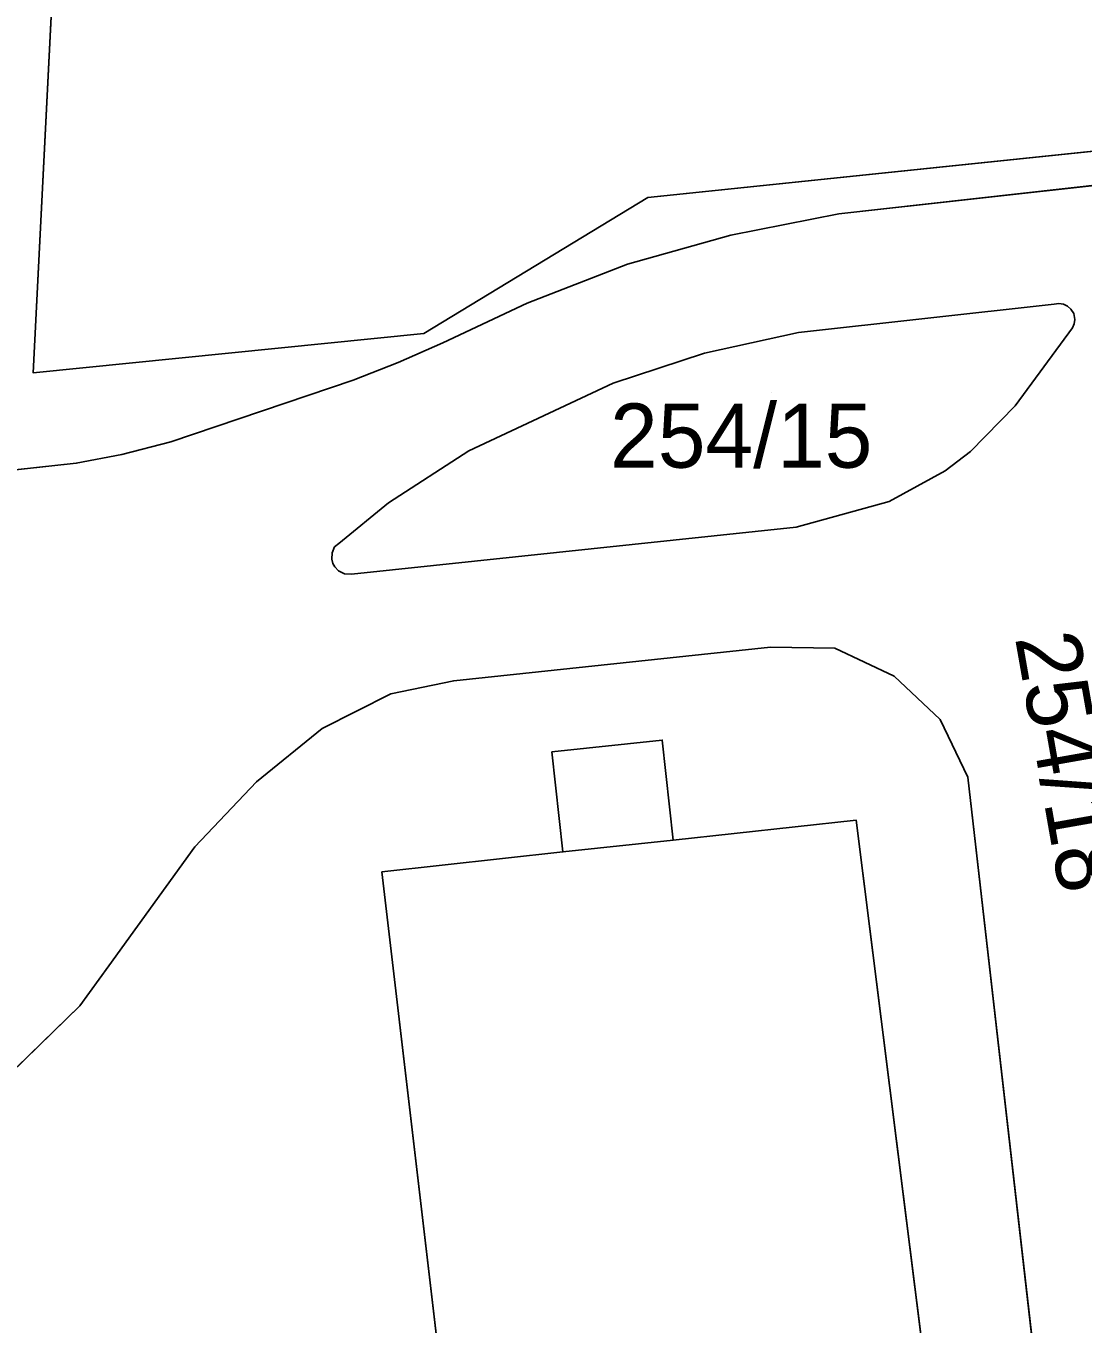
# Model space of a CAD drawing. Extents: x -263423 to -261326, y -1240067 to -1237864.
# Drawn here: x -263309.81 to -263276.85, y -1239534.41 to -1239493.95 of the extents above; entities that cross this region are included whole.
import ezdxf

# ---------------------------------------------------------------- set-up
doc = ezdxf.new("R2010")
doc.units = 0
for name, color, linetype in [('body_kn', 7, 'Continuous'), ('kladpar_druhypozemkov', 7, 'Continuous'), ('kladpar_hranice', 7, 'Continuous'), ('kladpar_parcelnecisla', 7, 'Continuous'), ('kladpar_plochy', 7, 'Continuous'), ('zappar_hrandruhpozemk', 7, 'Continuous')]:
    doc.layers.add(name, color=color, linetype=linetype)

msp = doc.modelspace()

# ---------------------------------------------------------------- linework, layer by layer
at = {"layer": 'body_kn'}
for p, q in [((-263290.42, -1239499.3), (-263290.42, -1239499.3)), ((-263284.46, -1239499.81), (-263284.46, -1239499.81)), ((-263287.83, -1239500.47), (-263287.83, -1239500.47)), ((-263291.05, -1239501.38), (-263291.05, -1239501.38)), ((-263294.18, -1239502.59), (-263294.18, -1239502.59)), ((-263277.75, -1239502.62), (-263277.75, -1239502.62)), ((-263277.61, -1239502.6), (-263277.61, -1239502.6)), ((-263277.46, -1239502.62), (-263277.46, -1239502.62)), ((-263277.33, -1239502.68), (-263277.33, -1239502.68)), ((-263277.23, -1239502.78), (-263277.23, -1239502.78)), ((-263277.14, -1239502.91), (-263277.14, -1239502.91)), ((-263277.13, -1239503.24), (-263277.13, -1239503.24)), ((-263277.11, -1239503.1), (-263277.11, -1239503.1)), ((-263297.4, -1239503.54), (-263297.4, -1239503.54)), ((-263285.72, -1239503.51), (-263285.72, -1239503.51)), ((-263277.18, -1239503.36), (-263277.18, -1239503.36)), ((-263296.81, -1239503.83), (-263296.81, -1239503.83)), ((-263298.2, -1239504.44), (-263298.2, -1239504.44)), ((-263288.65, -1239504.15), (-263288.65, -1239504.15)), ((-263309.59, -1239504.76), (-263309.59, -1239504.76)), ((-263299.61, -1239504.99), (-263299.61, -1239504.99)), ((-263291.5, -1239505.09), (-263291.5, -1239505.09)), ((-263278.97, -1239505.79), (-263278.97, -1239505.79)), ((-263305.29, -1239506.91), (-263305.29, -1239506.91)), ((-263296, -1239507.19), (-263296, -1239507.19)), ((-263280.36, -1239507.22), (-263280.36, -1239507.22)), ((-263308.24, -1239507.58), (-263308.24, -1239507.58)), ((-263306.82, -1239507.31), (-263306.82, -1239507.31)), ((-263281.15, -1239507.82), (-263281.15, -1239507.82)), ((-263298.51, -1239508.82), (-263298.51, -1239508.82)), ((-263298.51, -1239508.82), (-263298.51, -1239508.82)), ((-263282.9, -1239508.77), (-263282.9, -1239508.77)), ((-263285.79, -1239509.57), (-263285.79, -1239509.57)), ((-263300.05, -1239510.08), (-263300.05, -1239510.08)), ((-263300.26, -1239510.37), (-263300.26, -1239510.37)), ((-263300.19, -1239510.19), (-263300.19, -1239510.19)), ((-263300.27, -1239510.57), (-263300.27, -1239510.57)), ((-263300.24, -1239510.71), (-263300.24, -1239510.71)), ((-263300.18, -1239510.81), (-263300.18, -1239510.81)), ((-263300.07, -1239510.94), (-263300.07, -1239510.94)), ((-263299.88, -1239511.03), (-263299.88, -1239511.03)), ((-263299.66, -1239511.04), (-263299.66, -1239511.04)), ((-263286.59, -1239513.31), (-263286.59, -1239513.31)), ((-263284.59, -1239513.35), (-263284.59, -1239513.35)), ((-263296.47, -1239514.36), (-263296.47, -1239514.36)), ((-263282.74, -1239514.22), (-263282.74, -1239514.22)), ((-263298.43, -1239514.77), (-263298.43, -1239514.77)), ((-263281.3, -1239515.57), (-263281.3, -1239515.57)), ((-263300.57, -1239515.85), (-263300.57, -1239515.85)), ((-263293.41, -1239516.58), (-263293.41, -1239516.58)), ((-263289.97, -1239516.21), (-263289.97, -1239516.21)), ((-263280.44, -1239517.37), (-263280.44, -1239517.37)), ((-263302.62, -1239517.51), (-263302.62, -1239517.51)), ((-263283.92, -1239518.71), (-263283.92, -1239518.71)), ((-263289.63, -1239519.33), (-263289.63, -1239519.33)), ((-263304.54, -1239519.54), (-263304.54, -1239519.54)), ((-263293.07, -1239519.7), (-263293.07, -1239519.7)), ((-263293.07, -1239519.7), (-263293.07, -1239519.7)), ((-263298.71, -1239520.32), (-263298.71, -1239520.32)), ((-263298.71, -1239520.32), (-263298.71, -1239520.32)), ((-263307.23, -1239523.25), (-263307.23, -1239523.25)), ((-263308.13, -1239524.5), (-263308.13, -1239524.5))]:
    msp.add_line(p, q, dxfattribs=at)
at = {"layer": 'kladpar_druhypozemkov'}
msp.add_line((-263286.55, -1239505.37), (-263286.55, -1239505.37), dxfattribs=at)
at = {"layer": 'kladpar_hranice'}
for points in [[(-263266.8, -1239496.84), (-263270.06, -1239468.65), (-263281.55, -1239470.13), (-263281.76, -1239468.51), (-263288.17, -1239469.5), (-263287.73, -1239473.48), (-263293.36, -1239474.1), (-263293.55, -1239472.76), (-263301.84, -1239473.75), (-263301.82, -1239475.02), (-263310.21, -1239475.95), (-263308.82, -1239489.52), (-263309.59, -1239504.76), (-263297.4, -1239503.54), (-263290.42, -1239499.3), (-263266.8, -1239496.84)], [(-263266.8, -1239496.84), (-263290.42, -1239499.3), (-263297.4, -1239503.54), (-263309.59, -1239504.76), (-263308.82, -1239489.52), (-263310.21, -1239475.95), (-263301.82, -1239475.02), (-263301.84, -1239473.75), (-263293.55, -1239472.76), (-263293.36, -1239474.1), (-263287.73, -1239473.48), (-263288.17, -1239469.5), (-263281.76, -1239468.51), (-263281.55, -1239470.13), (-263270.06, -1239468.65), (-263266.8, -1239496.84)], [(-263299.61, -1239504.99), (-263298.2, -1239504.44), (-263296.81, -1239503.83), (-263294.18, -1239502.59), (-263291.05, -1239501.38), (-263287.83, -1239500.47), (-263284.46, -1239499.81), (-263267.57, -1239497.92), (-263265.57, -1239497.54), (-263263.67, -1239496.95), (-263261.73, -1239496.38), (-263259.76, -1239496.02), (-263245.74, -1239494.34)], [(-263267.57, -1239497.92), (-263284.46, -1239499.81), (-263287.83, -1239500.47), (-263291.05, -1239501.38), (-263294.18, -1239502.59), (-263296.81, -1239503.83), (-263298.2, -1239504.44), (-263299.61, -1239504.99), (-263305.29, -1239506.91), (-263306.82, -1239507.31), (-263308.24, -1239507.58), (-263325.13, -1239509.43)], [(-263298.51, -1239508.82), (-263296, -1239507.19), (-263291.5, -1239505.09), (-263288.65, -1239504.15), (-263285.72, -1239503.51), (-263277.75, -1239502.62), (-263277.61, -1239502.6), (-263277.46, -1239502.62), (-263277.33, -1239502.68), (-263277.23, -1239502.78), (-263277.14, -1239502.91), (-263277.11, -1239503.1), (-263277.13, -1239503.24), (-263277.18, -1239503.36), (-263278.97, -1239505.79), (-263280.36, -1239507.22), (-263281.15, -1239507.82), (-263282.9, -1239508.77), (-263285.79, -1239509.57), (-263299.66, -1239511.04), (-263299.88, -1239511.03), (-263300.07, -1239510.94), (-263300.18, -1239510.81), (-263300.24, -1239510.71), (-263300.27, -1239510.57), (-263300.26, -1239510.37), (-263300.19, -1239510.19), (-263300.05, -1239510.08), (-263298.51, -1239508.82)], [(-263296, -1239507.19), (-263298.51, -1239508.82), (-263300.05, -1239510.08), (-263300.19, -1239510.19), (-263300.26, -1239510.37), (-263300.27, -1239510.57), (-263300.24, -1239510.71), (-263300.18, -1239510.81), (-263300.07, -1239510.94), (-263299.88, -1239511.03), (-263299.66, -1239511.04), (-263285.79, -1239509.57), (-263282.9, -1239508.77), (-263281.15, -1239507.82), (-263280.36, -1239507.22), (-263278.97, -1239505.79), (-263277.18, -1239503.36), (-263277.13, -1239503.24), (-263277.11, -1239503.1), (-263277.14, -1239502.91), (-263277.23, -1239502.78), (-263277.33, -1239502.68), (-263277.46, -1239502.62), (-263277.61, -1239502.6), (-263277.75, -1239502.62), (-263285.72, -1239503.51), (-263288.65, -1239504.15), (-263291.5, -1239505.09), (-263296, -1239507.19)], [(-263335.45, -1239503.9), (-263329, -1239508.58), (-263327.88, -1239509.13), (-263326.44, -1239509.45), (-263325.13, -1239509.43), (-263308.24, -1239507.58), (-263306.82, -1239507.31), (-263305.29, -1239506.91), (-263299.61, -1239504.99)], [(-263335.27, -1239535.06), (-263333.76, -1239533.77), (-263331.92, -1239533.05), (-263319.02, -1239531.4), (-263316.26, -1239530.67), (-263313.36, -1239529.31), (-263312.5, -1239528.74), (-263308.13, -1239524.5), (-263307.23, -1239523.25), (-263304.54, -1239519.54), (-263302.62, -1239517.51), (-263300.57, -1239515.85), (-263298.43, -1239514.77), (-263296.47, -1239514.36), (-263286.59, -1239513.31), (-263284.59, -1239513.35), (-263282.74, -1239514.22), (-263281.3, -1239515.57), (-263280.44, -1239517.37), (-263278.03, -1239538.47)], [(-263278.03, -1239538.47), (-263280.44, -1239517.37), (-263281.3, -1239515.57), (-263282.74, -1239514.22), (-263284.59, -1239513.35), (-263286.59, -1239513.31), (-263296.47, -1239514.36), (-263298.43, -1239514.77), (-263300.57, -1239515.85), (-263302.62, -1239517.51), (-263304.54, -1239519.54), (-263307.23, -1239523.25), (-263308.13, -1239524.5), (-263312.5, -1239528.74), (-263313.36, -1239529.31), (-263316.26, -1239530.67), (-263319.02, -1239531.4), (-263331.92, -1239533.05), (-263333.76, -1239533.77), (-263335.27, -1239535.06)], [(-263298.71, -1239520.32), (-263293.07, -1239519.7), (-263293.41, -1239516.58), (-263289.97, -1239516.21), (-263289.63, -1239519.33), (-263283.92, -1239518.71), (-263280.36, -1239547.04), (-263281.94, -1239547.29), (-263280.21, -1239564.24), (-263281.86, -1239564.43), (-263281.16, -1239569.89), (-263281.15, -1239570.03), (-263281.1, -1239570.47), (-263283.25, -1239570.66), (-263283.06, -1239573.77), (-263287.38, -1239574.28), (-263287.7, -1239571.17), (-263290.24, -1239571.42), (-263290.36, -1239570.79), (-263291.07, -1239565.39), (-263292.72, -1239565.58), (-263294.64, -1239548.44), (-263295.4, -1239548.51), (-263298.71, -1239520.32)], [(-263280.36, -1239547.04), (-263283.92, -1239518.71), (-263289.63, -1239519.33), (-263289.97, -1239516.21), (-263293.41, -1239516.58), (-263293.07, -1239519.7), (-263298.71, -1239520.32), (-263295.4, -1239548.51)]]:
    msp.add_lwpolyline(points, dxfattribs=at)
at = {"layer": 'kladpar_plochy'}
for p, q in [((-263308.82, -1239489.52), (-263309.59, -1239504.76)), ((-263290.42, -1239499.3), (-263266.8, -1239496.84)), ((-263267.57, -1239497.92), (-263284.46, -1239499.81)), ((-263284.46, -1239499.81), (-263267.57, -1239497.92)), ((-263297.4, -1239503.54), (-263290.42, -1239499.3)), ((-263284.46, -1239499.81), (-263287.83, -1239500.47)), ((-263287.83, -1239500.47), (-263284.46, -1239499.81)), ((-263287.83, -1239500.47), (-263291.05, -1239501.38)), ((-263291.05, -1239501.38), (-263287.83, -1239500.47)), ((-263291.05, -1239501.38), (-263294.18, -1239502.59)), ((-263294.18, -1239502.59), (-263291.05, -1239501.38)), ((-263294.18, -1239502.59), (-263296.81, -1239503.83)), ((-263296.81, -1239503.83), (-263294.18, -1239502.59)), ((-263277.75, -1239502.62), (-263285.72, -1239503.51)), ((-263277.61, -1239502.6), (-263277.75, -1239502.62)), ((-263277.46, -1239502.62), (-263277.61, -1239502.6)), ((-263277.33, -1239502.68), (-263277.46, -1239502.62)), ((-263277.23, -1239502.78), (-263277.33, -1239502.68)), ((-263277.14, -1239502.91), (-263277.23, -1239502.78)), ((-263277.18, -1239503.36), (-263277.13, -1239503.24)), ((-263277.11, -1239503.1), (-263277.14, -1239502.91)), ((-263277.13, -1239503.24), (-263277.11, -1239503.1)), ((-263309.59, -1239504.76), (-263297.4, -1239503.54)), ((-263285.72, -1239503.51), (-263288.65, -1239504.15)), ((-263278.97, -1239505.79), (-263277.18, -1239503.36)), ((-263296.81, -1239503.83), (-263298.2, -1239504.44)), ((-263298.2, -1239504.44), (-263296.81, -1239503.83)), ((-263298.2, -1239504.44), (-263299.61, -1239504.99)), ((-263299.61, -1239504.99), (-263298.2, -1239504.44)), ((-263288.65, -1239504.15), (-263291.5, -1239505.09)), ((-263299.61, -1239504.99), (-263305.29, -1239506.91)), ((-263305.29, -1239506.91), (-263299.61, -1239504.99)), ((-263291.5, -1239505.09), (-263296, -1239507.19)), ((-263280.36, -1239507.22), (-263278.97, -1239505.79)), ((-263305.29, -1239506.91), (-263306.82, -1239507.31)), ((-263306.82, -1239507.31), (-263305.29, -1239506.91)), ((-263296, -1239507.19), (-263298.51, -1239508.82)), ((-263281.15, -1239507.82), (-263280.36, -1239507.22)), ((-263308.24, -1239507.58), (-263325.13, -1239509.43)), ((-263325.13, -1239509.43), (-263308.24, -1239507.58)), ((-263306.82, -1239507.31), (-263308.24, -1239507.58)), ((-263308.24, -1239507.58), (-263306.82, -1239507.31)), ((-263282.9, -1239508.77), (-263281.15, -1239507.82)), ((-263298.51, -1239508.82), (-263300.05, -1239510.08)), ((-263285.79, -1239509.57), (-263282.9, -1239508.77)), ((-263299.66, -1239511.04), (-263285.79, -1239509.57)), ((-263300.05, -1239510.08), (-263300.19, -1239510.19)), ((-263300.26, -1239510.37), (-263300.27, -1239510.57)), ((-263300.19, -1239510.19), (-263300.26, -1239510.37)), ((-263300.27, -1239510.57), (-263300.24, -1239510.71)), ((-263300.24, -1239510.71), (-263300.18, -1239510.81)), ((-263300.18, -1239510.81), (-263300.07, -1239510.94)), ((-263300.07, -1239510.94), (-263299.88, -1239511.03)), ((-263299.88, -1239511.03), (-263299.66, -1239511.04)), ((-263296.47, -1239514.36), (-263286.59, -1239513.31)), ((-263286.59, -1239513.31), (-263296.47, -1239514.36)), ((-263286.59, -1239513.31), (-263284.59, -1239513.35)), ((-263284.59, -1239513.35), (-263286.59, -1239513.31)), ((-263284.59, -1239513.35), (-263282.74, -1239514.22)), ((-263282.74, -1239514.22), (-263284.59, -1239513.35)), ((-263298.43, -1239514.77), (-263296.47, -1239514.36)), ((-263296.47, -1239514.36), (-263298.43, -1239514.77)), ((-263282.74, -1239514.22), (-263281.3, -1239515.57)), ((-263281.3, -1239515.57), (-263282.74, -1239514.22)), ((-263300.57, -1239515.85), (-263298.43, -1239514.77)), ((-263298.43, -1239514.77), (-263300.57, -1239515.85)), ((-263281.3, -1239515.57), (-263280.44, -1239517.37)), ((-263280.44, -1239517.37), (-263281.3, -1239515.57)), ((-263302.62, -1239517.51), (-263300.57, -1239515.85)), ((-263300.57, -1239515.85), (-263302.62, -1239517.51)), ((-263289.97, -1239516.21), (-263293.41, -1239516.58)), ((-263293.41, -1239516.58), (-263293.07, -1239519.7)), ((-263289.63, -1239519.33), (-263289.97, -1239516.21)), ((-263280.44, -1239517.37), (-263278.03, -1239538.47)), ((-263278.03, -1239538.47), (-263280.44, -1239517.37)), ((-263304.54, -1239519.54), (-263302.62, -1239517.51)), ((-263302.62, -1239517.51), (-263304.54, -1239519.54)), ((-263283.92, -1239518.71), (-263289.63, -1239519.33)), ((-263280.36, -1239547.04), (-263283.92, -1239518.71)), ((-263307.23, -1239523.25), (-263304.54, -1239519.54)), ((-263304.54, -1239519.54), (-263307.23, -1239523.25)), ((-263293.07, -1239519.7), (-263298.71, -1239520.32)), ((-263298.71, -1239520.32), (-263295.4, -1239548.51)), ((-263308.13, -1239524.5), (-263307.23, -1239523.25)), ((-263307.23, -1239523.25), (-263308.13, -1239524.5)), ((-263312.5, -1239528.74), (-263308.13, -1239524.5)), ((-263308.13, -1239524.5), (-263312.5, -1239528.74))]:
    msp.add_line(p, q, dxfattribs=at)
for points in [[(-263266.8, -1239496.84), (-263290.42, -1239499.3), (-263297.4, -1239503.54), (-263309.59, -1239504.76), (-263308.82, -1239489.52), (-263310.21, -1239475.95), (-263301.82, -1239475.02), (-263301.84, -1239473.75), (-263293.55, -1239472.76), (-263293.36, -1239474.1), (-263287.73, -1239473.48), (-263288.17, -1239469.5), (-263281.76, -1239468.51), (-263281.55, -1239470.13), (-263270.06, -1239468.65)], [(-263298.51, -1239508.82), (-263296, -1239507.19), (-263291.5, -1239505.09), (-263288.65, -1239504.15), (-263285.72, -1239503.51), (-263277.75, -1239502.62), (-263277.61, -1239502.6), (-263277.46, -1239502.62), (-263277.33, -1239502.68), (-263277.23, -1239502.78), (-263277.14, -1239502.91), (-263277.11, -1239503.1), (-263277.13, -1239503.24), (-263277.18, -1239503.36), (-263278.97, -1239505.79), (-263280.36, -1239507.22), (-263281.15, -1239507.82), (-263282.9, -1239508.77), (-263285.79, -1239509.57), (-263299.66, -1239511.04), (-263299.88, -1239511.03), (-263300.07, -1239510.94), (-263300.18, -1239510.81), (-263300.24, -1239510.71), (-263300.27, -1239510.57), (-263300.26, -1239510.37), (-263300.19, -1239510.19), (-263300.05, -1239510.08)], [(-263298.71, -1239520.32), (-263293.07, -1239519.7), (-263293.41, -1239516.58), (-263289.97, -1239516.21), (-263289.63, -1239519.33), (-263283.92, -1239518.71), (-263280.36, -1239547.04), (-263281.94, -1239547.29), (-263280.21, -1239564.24), (-263281.86, -1239564.43), (-263281.16, -1239569.89), (-263281.15, -1239570.03), (-263281.1, -1239570.47), (-263283.25, -1239570.66), (-263283.06, -1239573.77), (-263287.38, -1239574.28), (-263287.7, -1239571.17), (-263290.24, -1239571.42), (-263290.36, -1239570.79), (-263291.07, -1239565.39), (-263292.72, -1239565.58), (-263294.64, -1239548.44), (-263295.4, -1239548.51)]]:
    msp.add_lwpolyline(points, close=True, dxfattribs=at)
at = {"layer": 'zappar_hrandruhpozemk'}
msp.add_line((-263293.07, -1239519.7), (-263289.63, -1239519.33), dxfattribs=at)

# ---------------------------------------------------------------- texts
at = {"layer": 'kladpar_parcelnecisla'}
msp.add_text('254/15', height=2, dxfattribs=at).set_placement((-263291.597, -1239507.72))
msp.add_text('254/18', height=2, rotation=280, dxfattribs=at).set_placement((-263278.975, -1239513.018))

doc.saveas('drawing.dxf')
